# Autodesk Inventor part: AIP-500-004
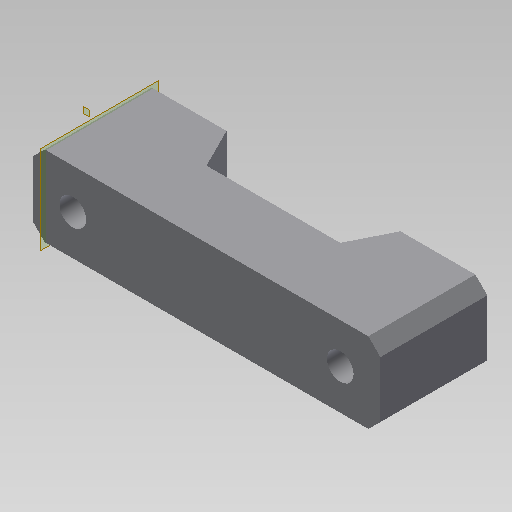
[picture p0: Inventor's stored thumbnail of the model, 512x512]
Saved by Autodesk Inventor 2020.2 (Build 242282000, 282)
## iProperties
Created: 2014-06
Part Number: AIP-500-004
Material: Ogólny
Document SubType Name: Modeling
Designer: F.Stasiak
Density: 1 g/cm^3
Appearance: Domyślna
Catalog Web Link: www.expertbooks.pl
Manager: www.cadconsulting.pl
Company: Fabian Stasiak CAD Consulting
Author: F.Stasiak
Subject: Zbiór ćwiczeń. Autodesk Inventor 2020. Kurs Professional
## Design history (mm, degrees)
sketch "Szkic1"
  geometry: L1 (150, -150)-(-1150, -150); L2 (-1150, -150)-(-1150, 150); L3 (-1150, 150)-(150, 150); L4 (150, 150)-(150, -150); L5 (0, 0)-(-1000, 0); C1 r 50 at (0, 0); C2 r 50 at (-1000, 0); 4 further points
  constraints: 10 end point, 3 midpoint, 2 centre point, 2 parallel, 2 perpendicular, 1 coincident, 1 equal radius, 1 horizontal, 1 point on line, 1 vertical alignment
  dimensions: "d2" = 100 diameter of C1; "d3" = 1000 distance of L5.end L5.start; "d4" = 1300 distance of L2.end L3.end; "d5" = 300 distance of L1.end L2.end
extrude "Wyciągnięcie proste1" new body sketch "Szkic1" distance "d6" = 400; taper "d7" = 0 deg
sketch "Szkic2"
  geometry: L1 (0, 0)-(1300, 0) reference; L2 (0, 400)-(1300, 400) reference; L3 (0, 0)-(0, 400) reference; L4 (975, 400)-(900, 250); L5 (900, 250)-(400, 250); L6 (400, 250)-(325, 400); 3 further points
  constraints: 6 end point, 2 midpoint, 2 point on line, 1 equal length, 1 perpendicular, 1 vertical alignment
  dimensions: "d8" = 150 distance between parallel lines of L5 L2; "d9" = 650 distance of L6.end L4.start; "d10" = 500 distance of L4.end L5.end
extrude "Wyciągnięcie proste2" cut sketch "Szkic2" extent not by distance; stored distance "d11" = 400; taper "d12" = 0 deg
node "Płaszczyzna konstrukcyjna1"
sketch "Szkic3"
  geometry: L1 (0, -300)-(0, 0) reference; L2 (30, -190)-(30, -110); A1 r 50 centre (0, -150) between (0, -200) and (30, -190); A2 r 50 centre (0, -150) between (30, -110) and (0, -100); 1 further point
  constraints: 4 point on circle, 2 centre point, 2 end point, 2 point on line, 1 midpoint, 1 parallel
  dimensions: "d27" = 30 distance between parallel lines of L1 L2
extrude "Wyciągnięcie proste3" join sketch "Szkic3" stored distance "d14" = 250; taper "d15" = 0 deg
node "Płaszczyzna konstrukcyjna2"
chamfer "Faza1" distance "d24" = 45; stored, may be unused: second distance "d25" = 2, angle "d26" = 45 deg
sketch "Szkic5"
  geometry: L1 (0, 0)-(250, 0) reference; L2 (250, 80)-(250, 0) reference; L3 (185, 40)-(65, 40); 4 further points
  constraints: 3 midpoint, 2 end point, 1 horizontal alignment, 1 perpendicular, 1 vertical alignment
  dimensions: "d28" = 120 distance of L3.start L3.end
hole "Otwór2" sketch "Szkic5" at (185, 40), (65, 40) diameter "d29" = 15; stored, may be unused: countersink angle "d33" = 90 deg, drill point angle "d35" = 118 deg; dims "d30" = 6, "d31" = 4, "d32" = 2, "d34" = 15
node "Bryła1"
